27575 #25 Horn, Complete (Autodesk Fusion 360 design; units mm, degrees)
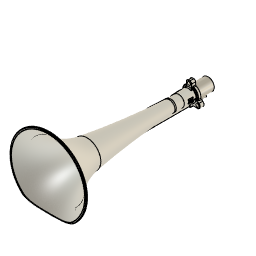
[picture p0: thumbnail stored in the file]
parameter "Bolt_Hole_Tolerance" = 1.5875 (= "( 1 / 16 ) * 1 in")
parameter "Dowel_Hole_Tolerance" = 0.0248 (= "( 1 / 1024 ) * 1 in")
canvas "Canvas1"
sketch "Main Profile" plane through (0, 0, 0) normal (1, 0, 0) x axis (0, 1, 0)
  line L1 (0, -22.225) -> (0, 22.225)
  line L2 (-53.975, 22.225) -> (0, 22.225)
  line L3 (-53.975, 44.45) -> (-53.975, 22.225)
  line L4 (-570.7062, 0) -> (0, 0)
  line L5 (-68.2625, 44.45) -> (-53.975, 44.45)
  line L6 (-53.975, -22.225) -> (0, -22.225)
  line L7 (-53.975, 22.225) -> (-53.975, -22.225)
  line L8 (-53.975, -38.1) -> (-53.975, -22.225)
  line L9 (-68.2625, -38.1) -> (-53.975, -38.1)
  line L10 (-68.2625, 44.45) -> (-68.2625, -38.1)
  line L11 (-138.2653, 17.1493) -> (0, 11.1125)
  line L12 (-63.5, 28.575) -> (-53.975, 28.575)
  line L13 (-63.5, 17.063) -> (-63.5, 28.575)
  line L14 (-138.1268, 20.3213) -> (-63.5, 17.063)
  line L15 (-570.7062, -136.525) -> (-570.7062, 136.525)
  line L16 (-68.2625, 17.2709) -> (-68.2625, 44.45)
  line L17 (9.1828, 34.925) -> (-68.2625, 34.925)
  line L18 (-34.1313, 22.225) -> (-34.1313, -22.225)
  line L19 (-431.6987, 0) -> (-431.6987, 46.0375)
  line L20 (-138.2653, -17.1493) -> (0, -11.1125)
  line L21 (-68.2625, -17.2709) -> (-68.2625, -38.1)
  line L22 (-68.2625, -17.2709) -> (-138.1268, -20.3213)
  line L23 (-532.6062, -136.525) -> (-570.7062, -136.525)
  line L24 (-532.6062, -123.825) -> (-532.6062, -136.525)
  line L25 (-570.7062, -123.825) -> (-532.6062, -123.825)
  line L26 (-570.7062, -136.525) -> (-570.7062, -123.825)
  line L27 (-565.9438, 136.525) -> (-570.7062, 136.525)
  line L28 (-565.9438, 129.9114) -> (-565.9438, 136.525)
  line L29 (-104.775, 20.1844) -> (-63.5, 22.225)
  line L30 (-324.4666, -34.925) -> (-68.2625, -34.925)
  arc A1 centre (-20.2125, 2721.0038) radius 2706.4304 clockwise from (-138.2653, 17.1493) to (-431.6987, 46.0375)
  arc A2 centre (-399.5974, 254.7204) radius 211.1375 clockwise from (-431.6987, 46.0375) to (-570.7062, 131.024)
  arc A3 centre (-20.2125, 2721.0038) radius 2703.2554 clockwise from (-138.1268, 20.3213) to (-431.216, 49.1756)
  arc A4 centre (-399.5974, 254.7204) radius 207.9625 clockwise from (-431.216, 49.1756) to (-570.7062, 136.525)
  arc A5 centre (-399.5974, -254.7204) radius 207.9625 clockwise from (-570.7062, -136.525) to (-431.216, -49.1756)
  arc A6 centre (-399.5974, -254.7204) radius 211.1375 clockwise from (-570.7062, -131.024) to (-431.6987, -46.0375)
  arc A7 centre (-20.2125, -2721.0038) radius 2703.2554 clockwise from (-431.216, -49.1756) to (-138.1268, -20.3213)
  arc A8 centre (-20.2125, -2721.0038) radius 2706.4304 clockwise from (-431.6987, -46.0375) to (-138.2653, -17.1493)
  arc A9 centre (-532.6062, -98.425) radius 38.1 clockwise from (-532.6062, -136.525) to (-570.7062, -98.425)
  arc A10 centre (-119.8256, 324.6126) radius 304.8 clockwise from (-104.775, 20.1844) to (-133.1208, 20.1027)
  point P4 (0, 0)
  point P1 (0, 0)
  point P7 (0, 0)
  point P13 (0, 11.1125)
  point P15 (-53.975, 28.575)
  point P21 (-570.7062, 0)
  point P8 (-570.7062, 0)
  point P22 (-68.2625, 17.2709)
  point P23 (-68.2625, 34.925)
  point P27 (-570.7062, 131.024)
  point P19 (-570.7062, 136.525)
  point P31 (-570.7062, 136.525)
  point P33 (-34.1313, -22.225)
  point P34 (-34.1313, 22.225)
  point P35 (-431.6987, 0)
  point P46 (0, -11.1125)
  point P14 (-138.2653, 17.1493)
  point P45 (-138.2653, -17.1493)
  point P18 (-138.1268, 20.3213)
  point P43 (-138.1268, -20.3213)
  point P25 (-431.6987, 46.0375)
  point P41 (-431.6987, -46.0375)
  point P40 (-570.7062, -131.024)
  point P29 (-431.216, 49.1756)
  point P38 (-431.216, -49.1756)
  point P37 (-570.7062, -136.525)
  point P47 (-68.2625, -17.2709)
  point P51 (-570.7062, -98.425)
  point P55 (-63.5, 22.225)
  point P57 (-68.2625, -34.925)
  point P59 (-133.1208, 20.1027)
  point P54 (-565.9438, 129.9114)
  point P58 (-324.4666, -34.925)
  point P2 (0, 22.225)
  point P5 (-53.975, 22.225)
  point P3 (0, -22.225)
  point P6 (-53.975, 44.45)
  point P9 (-68.2625, 44.45)
  point P16 (-63.5, 28.575)
  point P20 (-570.7062, -136.525)
  point P53 (-565.9438, 136.525)
  point P56 (-104.775, 20.1844)
  vertical L1
  coincident L1 P4
  coincident P1 P4
  midpoint P1 L1
  perpendicular L1 L2
  perpendicular L2 L3
  coincident P1 P7
  perpendicular L1 L4
  perpendicular L3 L5
  perpendicular L1 L6
  vertical L7
  perpendicular L6 L8
  perpendicular L8 L9
  vertical L10
  coincident L1 P13
  coincident L3 P15
  perpendicular L3 L12
  perpendicular L12 L13
  parallel L11 L14
  vertical L15
  midpoint L15 P21
  coincident P8 P21
  coincident L14 P22
  coincident L10 P22
  coincident L10 P23
  perpendicular L16 L17
  tangent L11 A1
  coincident L15 P27
  tangent A1 A2
  tangent L14 A3
  concentric A1 A3
  tangent A3 A4
  concentric A2 A4
  coincident P19 P31
  coincident L6 P33
  coincident L2 P34
  perpendicular L2 L18
  coincident L4 P35
  perpendicular L4 L19
  symmetric L4 P13 P46
  symmetric L4 P14 P45
  symmetric L4 P18 P43
  symmetric L4 P25 P41
  symmetric L4 A1 A8
  symmetric L4 P27 P40
  symmetric L4 A2 A6
  symmetric L4 P29 P38
  symmetric L4 A3 A7
  symmetric L4 P31 P37
  symmetric L4 A4 A5
  coincident L10 P47
  perpendicular L9 L21
  tangent A7 L22
  horizontal L23
  vertical L24
  horizontal L25
  vertical L26
  tangent L15 A9
  coincident L15 P51
  tangent L23 A9
  perpendicular L15 L27
  vertical L28
  coincident L13 P55
  coincident L10 P57
  horizontal L30
  coincident L14 P59
  tangent L29 A10
  tangent L14 A10
  coincident A4 P54
  coincident A7 P58
  dimension "d1" distance P2 P5 = 53.975 (= "2 1/8")
  dimension "d2" distance P2 P3 = 44.45 (= "1 3/4")
  dimension "d3" distance P6 L4 = 44.45 (= "1 3/4")
  dimension "d4" distance P6 P9 = 14.2875 (= "( 9 / 16 ) * 1 in")
  dimension "d5" distance L4 L9 = 38.1
  dimension "d6" distance P4 P13 = 11.1125 (= "( 7 / 16 ) * 1 in")
  dimension "d7" distance L11 L14 = 3.175 (= "( 1 / 8 ) * 1 in")
  dimension "d9" distance P15 P16 = 9.525 (= "( 3 / 8 ) * 1 in")
  dimension "d10" distance L4 L12 = 28.575
  dimension "d11" distance L4 L17 = 34.925 (= "1 3/8")
  dimension "d12" distance P19 P20 = 273.05 (= "10 3/4")
  dimension "d13" angle L4 L11 = 2.5
  dimension "d14" radius A1 = 2706.4304
  dimension "d15" radius A2 = 211.1375 (= "8 5/16")
  dimension "d17" distance L1 L18 = 34.1313 (= "1 11/32")
  dimension "d18" distance L15 L18 = 536.575 (= "21 1/8")
  dimension "d19" distance P25 P35 = 46.0375 (= "1 13/16")
  dimension "d23" distance L23 L25 = 12.7 (= "( 1 / 2 ) * 1 in")
  dimension "d24" radius A9 = 38.1 (= "1 1/2")
  dimension "d68" distance P19 P53 = 4.7625 (= "( 3 / 16 ) * 1 in")
  dimension "d114" distance P16 P55 = 6.35 (= "( 1 / 4 ) * 1 in")
  dimension "d115" distance L13 P56 = 41.275 (= "1 5/8")
  dimension "d117" distance L9 L30 = 3.175 (= "( 1 / 8 ) * 1 in")
  dimension "d153" radius A10 = 304.8
revolve "Revolve1" sketch "Main Profile" AlongAngle 360
extrude "Extrude1" cut sketch "Main Profile" profile of L15 A5 A6 L23 L24 L25 L26 A9 distance 139.7
sweep "Sweep5" sketch "Main Profile" TwistAngle 0 TaperAngle 0
sweep "Sweep6" TwistAngle 0 TaperAngle 0
mirror "Mirror3" mirrorStitchTolerance 0.1016
fillet "Fillet6" radius 101.6
fillet "Fillet8" radius 101.6
split "Split1"
remove_body "RemoveBody1"
delete_face "DeleteFace6"
delete_face "DeleteFace7"
mirror "Mirror4" mirrorStitchTolerance 0.1016
fillet "Fillet9" radius 1.5875 (= "( 1 / 16 ) * 1 in")
canvas "Canvas2"
sketch "Flange Profile" plane through (0, -53.975, 0) normal (0, 1, 0) x axis (-1, 0, 0)
  line L1 (0, 34.925) -> (0, 0)
  line L2 (0, 44.45) -> (0, 34.925)
  line L3 (3.175, 44.45) -> (-3.175, 44.45)
  line L4 (9.525, 31.1085) -> (9.525, 38.1)
  line L5 (-30.2459, -17.4625) -> (0, 0)
  line L6 (30.2459, -17.4625) -> (0, 0)
  line L7 (30.2459, -26.9875) -> (15.0812, -26.9875)
  line L8 (29.9633, -6.3008) -> (35.0084, -9.2136)
  line L9 (0, -31.75) -> (0, 0)
  line L10 (0, -38.1) -> (0, -31.75)
  line L11 (3.9688, -38.1) -> (-3.9688, -38.1)
  line L12 (15.0812, -26.9875) -> (3.9688, -38.1)
  line L13 (-15.0812, -26.9875) -> (-3.9688, -38.1)
  line L14 (-30.2459, -26.9875) -> (-15.0812, -26.9875)
  line L15 (-29.9633, -6.3008) -> (-35.0084, -9.2136)
  line L16 (-9.525, 31.1085) -> (-9.525, 38.1)
  line L17 (9.525, 20.0805) -> (9.525, 31.1085)
  line L18 (-9.525, 20.0805) -> (-9.525, 31.1085)
  line L19 (22.1527, -1.7913) -> (29.9633, -6.3008)
  line L20 (-22.1527, -1.7913) -> (-29.9633, -6.3008)
  circle C1 centre (0, 0) radius 22.225
  circle C2 centre (0, 34.925) radius 5.5563
  arc A1 centre (3.175, 38.1) radius 6.35 clockwise from (3.175, 44.45) to (9.525, 38.1)
  arc A2 centre (15.875, 31.1085) radius 6.35 clockwise from (12.9886, 25.4524) to (9.525, 31.1085)
  arc A3 centre (0, 0) radius 28.575 clockwise from (12.9886, 25.4524) to (28.3957, -3.196)
  circle C3 centre (-30.2459, -17.4625) radius 5.5563
  circle C4 centre (30.2459, -17.4625) radius 5.5563
  arc A4 centre (30.2459, -17.4625) radius 9.525 clockwise from (35.0084, -9.2136) to (30.2459, -26.9875)
  arc A5 centre (31.5508, -3.5512) radius 3.175 clockwise from (29.9633, -6.3008) to (28.3957, -3.196)
  circle C5 centre (0, -31.75) radius 3.9688
  arc A6 centre (-30.2459, -17.4625) radius 9.525 clockwise from (-30.2459, -26.9875) to (-35.0084, -9.2136)
  arc A7 centre (-31.5508, -3.5512) radius 3.175 clockwise from (-28.3957, -3.196) to (-29.9633, -6.3008)
  arc A8 centre (0, 0) radius 28.575 clockwise from (-28.3957, -3.196) to (-12.9886, 25.4524)
  arc A9 centre (-15.875, 31.1085) radius 6.35 clockwise from (-9.525, 31.1085) to (-12.9886, 25.4524)
  arc A10 centre (-3.175, 38.1) radius 6.35 clockwise from (-9.525, 38.1) to (-3.175, 44.45)
  circle C6 centre (0, 0) radius 28.575
  point P1 (0, 0)
  point P3 (0, 0)
  point P4 (0, 34.925)
  point P5 (0, 34.925)
  point P6 (0, 34.925)
  point P10 (0, 44.45)
  point P7 (0, 44.45)
  point P30 (0, 0)
  point P31 (0, -31.75)
  point P32 (0, -31.75)
  point P33 (0, -31.75)
  point P37 (0, -38.1)
  point P34 (0, -38.1)
  point P9 (3.175, 44.45)
  point P52 (-3.175, 44.45)
  point P11 (9.525, 38.1)
  point P50 (-9.525, 38.1)
  point P13 (9.525, 31.1085)
  point P49 (-9.525, 31.1085)
  point P14 (12.9886, 25.4524)
  point P47 (-12.9886, 25.4524)
  point P16 (28.3957, -3.196)
  point P45 (-28.3957, -3.196)
  point P24 (15.0812, -26.9875)
  point P39 (-15.0812, -26.9875)
  point P25 (30.2459, -26.9875)
  point P40 (-30.2459, -26.9875)
  point P26 (35.0084, -9.2136)
  point P42 (-35.0084, -9.2136)
  point P28 (29.9633, -6.3008)
  point P43 (-29.9633, -6.3008)
  point P36 (3.9688, -38.1)
  point P38 (-3.9688, -38.1)
  point P53 (9.525, 20.0805)
  point P54 (-9.525, 20.0805)
  point P55 (22.1527, -1.7913)
  point P56 (-22.1527, -1.7913)
  point P35 (-3.9688, -38.1)
  point P19 (0, 0)
  coincident P1 P3
  vertical L1
  coincident P4 P5
  coincident P5 P6
  parallel L1 L2
  horizontal L3
  coincident L3 P10
  midpoint L3 P10
  coincident P7 P10
  tangent L3 A1
  vertical L4
  tangent A1 L4
  tangent L4 A2
  tangent A2 A3
  concentric C1 A3
  horizontal L7
  tangent L7 A4
  concentric C4 A4
  tangent A4 L8
  tangent L8 A5
  tangent A3 A5
  coincident P1 P30
  vertical L9
  coincident P31 P32
  coincident P32 P33
  parallel L9 L10
  horizontal L11
  midpoint L11 P37
  coincident P34 P37
  symmetric L1 P9 P52
  symmetric L1 P11 P50
  symmetric L1 A1 A10
  symmetric L1 P13 P49
  symmetric L1 P14 P47
  symmetric L1 A2 A9
  symmetric L1 P16 P45
  symmetric L1 A3 A8
  symmetric L1 P24 P39
  symmetric L1 P25 P40
  symmetric L1 P26 P42
  symmetric L1 A4 A6
  symmetric L1 P28 P43
  symmetric L1 A5 A7
  symmetric L1 P36 P38
  coincident C1 P53
  tangent A2 L17
  tangent A9 L18
  coincident C1 P54
  coincident C1 P55
  tangent A5 L19
  coincident C1 P56
  tangent A7 L20
  dimension "d95" distance P3 P4 = 34.925 (= "1 3/8")
  dimension "d96" diameter C2 = 11.1125 (= "( 3 / 8 ) * 1 in + Bolt_Hole_Tolerance")
  dimension "d97" radius A1 = 6.35 (= "( 1 / 4 ) * 1 in")
  dimension "d98" distance P1 L3 = 44.45 (= "1 3/4")
  dimension "d99" distance P5 L4 = 9.525 (= "( 3 / 8 ) * 1 in")
  dimension "d100" radius A2 = 6.35 (= "( 1 / 4 ) * 1 in")
  dimension "d101" radius A3 = 28.575 (= "1 1/8")
  dimension "d104" radius A4 = 9.525 (= "( 3 / 8 ) * 1 in")
  dimension "d105" angle L7 L8 = 30
  dimension "d106" radius A5 = 3.175 (= "( 1 / 8 ) * 1 in")
  dimension "d107" distance P30 P31 = 31.75 (= "1 1/4")
  dimension "d108" diameter C5 = 7.9375 (= "( 5 / 16 ) * 1 in")
  dimension "d109" distance P35 P36 = 7.9375 (= "( 5 / 16 ) * 1 in")
  dimension "d110" angle L7 L12 = 135
  dimension "d111" distance P19 L11 = 38.1 (= "1 1/2")
  dimension "d103" C-Pattern1-Angle = 360
extrude "Extrude2" add sketch "Flange Profile" profile of C1 C2 L3 A1 L4 C3 C4 L7 A4 L8 C5 L11 L12 L13 L14 A6 L15 L16 A10 L17 L18 L19 L20 against normal blind 14.2875 (magnitude of "( -9 / 16 ) * 1 in")
delete_face "DeleteFace8"
extrude "Extrude3" add sketch "Main Profile" profile of A7 L21 L22 L30 distance 6.35 (= "( 1 / 4 ) * 1 in")
delete_face "DeleteFace9"
fillet "Fillet10" radius 304.8
fillet "Fillet11" radius 3.175 (= "( 1 / 8 ) * 1 in")
fillet "Fillet12" radius 1.5875 (= "( 1 / 16 ) * 1 in")
fillet "Fillet13" radius 3.175 (= "( 1 / 8 ) * 1 in")
fillet "Fillet14" radius 1.5875 (= "( 1 / 16 ) * 1 in")
fillet "Fillet15" radius 0.7937 (= "( 1 / 32 ) * 1 in")
extrude "Extrude4" cut sketch "Flange Profile" profile of C2 C3 C4 against normal blind 14.3002
extrude "Extrude5" cut sketch "Flange Profile" profile of C5 against normal blind 9.525 (magnitude of "( -3 / 8 ) * 1 in")
sketch "Main Profile" plane through (0, -63.5, 0) normal (0, 1, 0) x axis (-1, 0, 0)
  circle C1 centre (0, -31.75) radius 3.9687
  circle C2 centre (0, -31.75) radius 3.175
  concentric C1 C2
  dimension "d137" diameter C2 = 6.35 (= "( 1 / 4 ) * 1 in")
extrude "Extrude1" new body sketch "Main Profile" along normal blind 53.975 (= "2 1/8") bodies "27284 Orifice Pin #2"
offset_faces "OffsetFaces1"
work_plane "WorkPlane1" RotateAngle -180
sketch "Orifice & Number Profile" plane through (0, -43.2509, -35.7188) normal (0, 0, -1) x axis (1, 0, 0)
  line L1 (3.9688, -33.7259) -> (-3.9687, -33.7259)
  line L2 (3.9688, 20.2491) -> (-3.9687, 20.2491)
  line L3 (0, 20.2491) -> (0, -33.7259)
  line L4 (-22.225, -43.2509) -> (22.225, -43.2509)
  line L5 (1.5875, -9.1196) -> (1.5875, -33.7259)
  line L6 (0, -9.1196) -> (1.5875, -9.1196)
  circle C1 centre (0, -9.1196) radius 1.5875
  point P6 (0, -33.7259)
  point P7 (0, 20.2491)
  point P8 (0, -9.1196)
  point P11 (1.5875, -33.7259)
  point P13 (0, -9.1196)
  point P12 (1.5875, -9.1196)
  midpoint L1 P6
  midpoint L2 P7
  coincident L3 P8
  coincident L1 P11
  perpendicular L1 L5
  coincident L3 P13
  perpendicular L3 L6
  coincident P8 P13
  dimension "d143" diameter C1 = 3.175 (= "( 1 / 8 ) * 1 in")
  dimension "d144" distance P8 L4 = 34.1313
  dimension "d145" distance P12 P13 = 1.5875 (= "( 1 / 16 ) * 1 in")
  dimension "d146" Text1-Height = 3.175 (= "( 1 / 8 ) * 1 in")
emboss "Emboss1" sketch "Orifice & Number Profile" Depth -0.1984 (= "( -1 / 128 ) * 1 in") Horizontal Distance 0 Vertical Distance 0 Rotation Angle 0
extrude "Extrude2" cut sketch "Orifice & Number Profile" profile of C1 against normal blind 3.175 (magnitude of "( -1 / 8 ) * 1 in")
sketch "Branding Profile 1" plane through (0, 0, 0) normal (0, 0, 1) x axis (1, 0, 0)
  line L1 (49.1756, -431.216) -> (-49.1756, -431.216)
  curve K1 (-4.4177, -138.1268) -> (-4.5392, -298.3662)
  curve K2 (-4.5392, -298.3662) -> (-4.4127, -306.9422)
  curve K3 (-4.4127, -306.9422) -> (-1.6572, -346.2553)
  curve K4 (-1.6572, -346.2553) -> (1.6572, -346.2553)
  curve K5 (1.6572, -346.2553) -> (4.4127, -306.9422)
  curve K6 (4.4127, -306.9422) -> (4.5392, -298.3662)
  curve K7 (4.5392, -298.3662) -> (4.4177, -138.1268)
  line L2 (20.3213, -138.1268) -> (-20.3213, -138.1268)
  line L3 (-4.4142, -133.1208) -> (-4.4177, -138.1268)
  line L4 (20.3213, -138.1268) -> (-20.3213, -138.1268)
  line L5 (4.4177, -138.1268) -> (4.4142, -133.1208)
  line L6 (20.1027, -133.1208) -> (-20.1027, -133.1208)
  curve K8 (-4.4156, -104.775) -> (-4.4142, -133.1208)
  line L7 (20.1027, -133.1208) -> (-20.1027, -133.1208)
  curve K9 (4.4142, -133.1208) -> (4.4156, -104.775)
  line L8 (20.1844, -104.775) -> (-20.1844, -104.775)
  line L9 (-10.3604, -71.2807) -> (10.3604, -71.2807)
  curve K10 (-10.3604, -71.2807) -> (-10.3702, -65.0091)
  line L10 (-22.1504, -65.0091) -> (-10.3702, -65.0091)
  curve K11 (-22.1357, -65.0091) -> (-21.8309, -71.2807)
  line L11 (-21.8309, -71.2807) -> (-4.4402, -71.2807)
  curve K12 (-4.4402, -71.2807) -> (-4.4156, -104.775)
  line L12 (20.1844, -104.775) -> (-20.1844, -104.775)
  curve K13 (4.4156, -104.775) -> (4.4402, -71.2807)
  line L13 (4.4402, -71.2807) -> (21.8309, -71.2807)
  curve K14 (21.8309, -71.2807) -> (22.1357, -65.0091)
  line L14 (10.3702, -65.0091) -> (22.1504, -65.0091)
  curve K15 (10.3702, -65.0091) -> (10.3604, -71.2807)
  line L15 (-20.1844, -104.775) -> (-21.8309, -71.2807)
  line L16 (-21.7878, -76.2) -> (-20.0037, -76.1192)
  line L17 (-20.0636, -114.261) -> (-21.7878, -76.2)
  line L18 (-18.2795, -114.1801) -> (-20.0636, -114.261)
  line L19 (-20.0037, -76.1192) -> (-18.2795, -114.1801)
  line L20 (-24.6635, -68.2625) -> (-34.6116, -68.2625)
  line L21 (-20.0959, -126.961) -> (-18.3123, -127.0528)
  line L22 (-23.5228, -193.5478) -> (-20.0959, -126.961)
  line L23 (-21.7392, -193.6396) -> (-23.5228, -193.5478)
  line L24 (-18.3123, -127.0528) -> (-21.7392, -193.6396)
  line L25 (0, 15.24) -> (0, 0)
  line L26 (20.1844, -104.775) -> (21.8309, -71.2807)
  line L27 (20.004, -76.1123) -> (21.7878, -76.2)
  line L28 (19.3804, -88.797) -> (20.004, -76.1123)
  line L29 (21.1642, -88.8847) -> (19.3804, -88.797)
  line L30 (21.7878, -76.2) -> (21.1642, -88.8847)
  line L31 (34.6116, -68.2625) -> (24.6635, -68.2625)
  arc A1 centre (-326.4604, -119.8309) radius 306.6458 clockwise from (-20.1844, -104.775) to (-20.1027, -133.1208)
  arc A2 centre (-8953.3117, 254.4038) radius 8941.6105 clockwise from (-20.1027, -133.1208) to (-20.3213, -138.1268)
  arc A3 centre (-2734.9134, -18.8431) radius 2717.2117 clockwise from (-20.3213, -138.1268) to (-49.1756, -431.216)
  arc A4 centre (326.4604, -119.8309) radius 306.6458 clockwise from (20.1027, -133.1208) to (20.1844, -104.775)
  arc A5 centre (2734.9134, -18.8431) radius 2717.2117 clockwise from (49.1756, -431.216) to (20.3213, -138.1268)
  arc A6 centre (8953.3117, 254.4038) radius 8941.6105 clockwise from (20.3213, -138.1268) to (20.1027, -133.1208)
  point P34 (-21.8309, -71.2807)
  point P46 (-21.8309, -71.2807)
  point P28 (-20.1844, -104.775)
  point P47 (-20.1844, -104.775)
  point P20 (-20.1027, -133.1208)
  point P48 (-20.1027, -133.1208)
  point P12 (-20.3213, -138.1268)
  point P50 (-20.3213, -138.1268)
  point P2 (-49.1756, -431.216)
  point P53 (-49.1756, -431.216)
  point P52 (-20.3213, -138.1268)
  point P59 (-21.5895, -76.191)
  point P60 (-19.8653, -114.252)
  point P67 (-23.3246, -193.558)
  point P68 (-19.8977, -126.9712)
  point P1 (0, 0)
  point P69 (0, 0)
  point P71 (21.8309, -71.2807)
  point P72 (20.1844, -104.775)
  point P74 (20.1027, -133.1208)
  point P79 (20.3213, -138.1268)
  point P77 (20.3213, -138.1268)
  point P76 (49.1756, -431.216)
  point P84 (21.5896, -76.1903)
  point P85 (20.966, -88.8749)
  point P57 (-20.0636, -114.261)
  point P56 (-21.7878, -76.2)
  point P64 (-20.0959, -126.961)
  point P65 (-23.5228, -193.5478)
  point P66 (-21.7392, -193.6396)
  point P80 (21.7878, -76.2)
  point P83 (21.1642, -88.8847)
  coincident P34 P46
  coincident P28 P47
  tangent L15 A1
  coincident P20 P48
  coincident P12 P50
  tangent A1 A2
  coincident P2 P53
  coincident P12 P52
  tangent A2 A3
  perpendicular L17 L18
  perpendicular L16 L17
  perpendicular L16 L19
  coincident L16 P59
  coincident L15 P59
  coincident A1 P60
  coincident L18 P60
  perpendicular L21 L22
  perpendicular L22 L23
  perpendicular L23 L24
  coincident A3 P67
  coincident L23 P67
  coincident A1 P68
  coincident L21 P68
  coincident P1 P69
  vertical L25
  symmetric P46 L25 P71
  symmetric P47 L25 P72
  symmetric P48 L25 P74
  symmetric A1 L25 A4
  symmetric P50 L25 P79
  symmetric A2 L25 A6
  symmetric P52 L25 P77
  symmetric P53 L25 P76
  symmetric A3 L25 A5
  perpendicular L26 L27
  perpendicular L27 L28
  perpendicular L26 L29
  perpendicular L29 L30
  coincident L27 P84
  coincident L26 P84
  coincident L29 P85
  coincident L26 P85
  dimension "d154" distance P57 P60 = 0.1984 (= "( 1 / 128 ) * 1 in")
  dimension "d155" distance P56 P59 = 0.1984 (= "d154")
  dimension "d156" distance P56 L20 = 7.9375 (= "( 5 / 16 ) * 1 in")
  dimension "d157" distance L19 P59 = 1.5875 (= "( 1 / 16 ) * 1 in")
  dimension "d158" distance P56 P57 = 38.1 (= "1 1/2")
  dimension "d159" distance P64 P68 = 0.1984 (= "d160")
  dimension "d160" distance P65 P67 = 0.1984 (= "( 1 / 128 ) * 1 in")
  dimension "d161" distance P66 P67 = 1.5875 (= "( 1 / 16 ) * 1 in")
  dimension "d162" distance P57 P64 = 12.7 (= "( 1 / 2 ) * 1 in")
  dimension "d163" distance P64 P65 = 66.675 (= "2 5/8")
  dimension "d164" distance L30 P84 = 0.1984 (= "( 1 / 128 ) * 1 in")
  dimension "d165" distance L26 L28 = 1.5875 (= "( 1 / 16 ) * 1 in")
  dimension "d166" distance P80 L31 = 7.9375 (= "( 5 / 16 ) * 1 in")
  dimension "d167" distance P80 P83 = 12.7 (= "( 1 / 2 ) * 1 in")
extrude "Extrude6" add sketch "Branding Profile 1" profile of L2 L4 L6 L7 L8 L12 L15 A1 A2 A3 L16 L17 L18 L19 L21 L22 L23 L24 distance 19.05 (= "( 3 / 4 ) * 1 in")
delete_face "DeleteFace10"
extrude "Extrude7" add sketch "Branding Profile 1" profile of L26 L27 L28 L29 L30 distance 9.525 (= "( 3 / 8 ) * 1 in")
fillet "Fillet16" radius 6.35 (= "( 1 / 4 ) * 1 in")
fillet "Fillet17" radius 3.175 (= "( 1 / 8 ) * 1 in")
fillet "Fillet18" radius 0.7937 (= "( 1 / 32 ) * 1 in")
sketch "Branding Profile 2" plane through (-25.188, -1.1411, 0) normal (-0.999, -0.0453, 0) x axis (0.0453, -0.999, 0)
  curve K1 (75.1359, -8.7898) -> (75.9363, -9.525)
  line L1 (104.0174, -9.525) -> (75.9363, -9.525)
  line L2 (112.415, -9.525) -> (104.0174, -9.525)
  curve K2 (112.415, -9.525) -> (113.2359, -8.7717)
  line L3 (113.2359, 8.7717) -> (113.2359, -8.7717)
  curve K3 (113.2359, 8.7717) -> (112.415, 9.525)
  line L4 (104.0174, 9.525) -> (112.415, 9.525)
  line L5 (75.9363, 9.525) -> (104.0174, 9.525)
  curve K4 (75.9363, 9.525) -> (75.1359, 8.7898)
  line L6 (75.1359, -8.7898) -> (75.1359, 8.7898)
  line L7 (93.251, 3.8359) -> (93.3442, 3.2617)
  line L8 (93.3764, -4.2813) -> (93.3764, -2.0198)
  line L9 (100.3887, -6.011) -> (97.0133, -5.5871)
  line L10 (94.139, 5.2738) -> (91.0873, 5.2738)
  line L11 (94.8829, -5.0326) -> (94.8829, -1.5281)
  line L12 (94.5336, 3.3576) -> (94.5336, 4.8791)
  line L13 (105.4604, -6.6138) -> (105.4604, 6.9982)
  line L14 (103.2461, -6.7165) -> (102.4928, -6.4572)
  line L15 (108.3757, -0.592) -> (108.3757, 0.1613)
  line L16 (109.6737, -8.4438) -> (109.6737, -7.6149)
  line L17 (103.7454, 6.3232) -> (103.7454, -6.3604)
  line L18 (107.4715, -0.9686) -> (107.999, -0.9686)
  line L19 (107.0949, -5.948) -> (107.0949, -1.3453)
  line L20 (109.5803, 7.8519) -> (109.5803, 8.6696)
  line L21 (107.0949, 0.9145) -> (107.0949, 6.3029)
  line L22 (102.4928, 6.42) -> (103.2461, 6.6793)
  line L23 (92.3058, 4.1584) -> (92.8719, 4.1584)
  line L24 (107.0949, 0.9145) -> (107.0949, -1.3453)
  line L25 (107.999, 0.5379) -> (107.4715, 0.5379)
  line L26 (100.8123, -4.8781) -> (100.8123, -5.6373)
  line L27 (102.2388, -6.1011) -> (102.2388, 6.0639)
  line L28 (97.8604, -3.8429) -> (97.8604, 5.1103)
  line L29 (98.1902, -4.2166) -> (100.4826, -4.5044)
  line L30 (94.5928, -0.6393) -> (92.0053, 2.9021)
  line L31 (97.4838, 5.487) -> (96.7305, 5.487)
  line L32 (96.3539, -4.8397) -> (96.3539, 5.1103)
  line L33 (92.9923, -4.6653) -> (92.0272, -4.6653)
  line L34 (91.2758, -5.4092) -> (94.5063, -5.4092)
  line L35 (87.1003, 4.6563) -> (88.4353, 4.3319)
  line L36 (88.6887, 5.7567) -> (85.3656, 6.5641)
  line L37 (89.1011, 4.8553) -> (89.1011, 5.2322)
  line L38 (91.9218, 3.5592) -> (91.9218, 3.7743)
  line L39 (105.8994, -7.2984) -> (109.1399, -8.7861)
  line L40 (86.2306, 1.0264) -> (86.2306, 3.9726)
  line L41 (90.6166, 2.3877) -> (90.6166, 4.8031)
  line L42 (91.9218, 3.158) -> (91.9218, 3.5592)
  line L43 (107.325, 6.6498) -> (109.3502, 7.5049)
  line L44 (80.4244, 8.1969) -> (79.8041, 8.6312)
  line L45 (87.0587, 0.5429) -> (86.7141, 0.5429)
  line L46 (89.3306, -5.0959) -> (89.3306, -5.528)
  line L47 (88.9498, -6.0315) -> (85.5568, -6.9922)
  line L48 (87.5422, -0.4801) -> (87.5422, 0.0594)
  line L49 (86.7141, -0.9636) -> (87.0587, -0.9636)
  line L50 (91.6431, -4.2813) -> (91.6431, -2.0448)
  line L51 (90.8992, -2.0448) -> (90.8992, -5.0326)
  line L52 (86.2306, 1.0264) -> (86.2306, -1.4472)
  line L53 (83.3482, -6.7697) -> (83.3482, -7.1367)
  line L54 (84.7241, -6.3626) -> (84.7241, 6.0597)
  line L55 (109.0571, 9.0165) -> (105.9207, 7.6922)
  line L56 (87.0677, -5.0926) -> (88.7109, -4.6273)
  line L57 (109.4542, -7.2726) -> (107.3144, -6.2903)
  line L58 (91.2665, -1.6682) -> (91.2758, -1.6682)
  line L59 (81.392, -6.7702) -> (82.4605, -6.2258)
  line L60 (86.2306, -4.4596) -> (86.2306, -1.4472)
  line L61 (80.6263, -6.301) -> (80.6263, 7.809)
  line L62 (82.9551, -7.7782) -> (80.241, -9.1611)
  line L63 (93.0863, -1.131) -> (90.6984, 2.1371)
  line L64 (78.9918, -8.3956) -> (78.9918, 8.2084)
  arc A1 centre (92.9923, -4.2813) radius 0.3841 clockwise from (93.3764, -4.2813) to (92.9923, -4.6653)
  arc A2 centre (94.5063, -5.0326) radius 0.3766 clockwise from (94.8829, -5.0326) to (94.5063, -5.4092)
  arc A3 centre (93.9351, 3.3576) radius 0.5986 clockwise from (94.5336, 3.3576) to (93.3442, 3.2617)
  arc A4 centre (91.0414, 2.3877) radius 0.4248 clockwise from (90.6984, 2.1371) to (90.6166, 2.3877)
  arc A5 centre (109.2036, 7.8519) radius 0.3766 clockwise from (109.5803, 7.8519) to (109.3502, 7.5049)
  arc A6 centre (100.4357, -5.6373) radius 0.3766 clockwise from (100.8123, -5.6373) to (100.3887, -6.011)
  arc A7 centre (109.2971, -7.6149) radius 0.3766 clockwise from (109.4542, -7.2726) to (109.6737, -7.6149)
  arc A8 centre (102.6155, 6.0639) radius 0.3766 clockwise from (102.2388, 6.0639) to (102.4928, 6.42)
  arc A9 centre (109.2036, 8.6696) radius 0.3766 clockwise from (109.0571, 9.0165) to (109.5803, 8.6696)
  arc A10 centre (107.4715, -5.948) radius 0.3766 clockwise from (107.3144, -6.2903) to (107.0949, -5.948)
  arc A11 centre (109.2971, -8.4438) radius 0.3766 clockwise from (109.6737, -8.4438) to (109.1399, -8.7861)
  arc A12 centre (107.4715, 0.9145) radius 0.3766 clockwise from (107.4715, 0.5379) to (107.0949, 0.9145)
  arc A13 centre (107.4715, -1.3453) radius 0.3766 clockwise from (107.0949, -1.3453) to (107.4715, -0.9686)
  arc A14 centre (102.6155, -6.1011) radius 0.3766 clockwise from (102.4928, -6.4572) to (102.2388, -6.1011)
  arc A15 centre (100.4357, -4.8781) radius 0.3766 clockwise from (100.4826, -4.5044) to (100.8123, -4.8781)
  arc A16 centre (106.2137, 6.9982) radius 0.7533 clockwise from (105.4604, 6.9982) to (105.9207, 7.6922)
  arc A17 centre (103.3687, 6.3232) radius 0.3766 clockwise from (103.2461, 6.6793) to (103.7454, 6.3232)
  arc A18 centre (94.139, 4.8791) radius 0.3947 clockwise from (94.139, 5.2738) to (94.5336, 4.8791)
  arc A19 centre (92.8719, 3.7743) radius 0.3841 clockwise from (92.8719, 4.1584) to (93.251, 3.8359)
  arc A20 centre (103.3687, -6.3604) radius 0.3766 clockwise from (103.7454, -6.3604) to (103.2461, -6.7165)
  arc A21 centre (106.2137, -6.6138) radius 0.7533 clockwise from (105.8994, -7.2984) to (105.4604, -6.6138)
  arc A22 centre (97.4838, 5.1103) radius 0.3766 clockwise from (97.4838, 5.487) to (97.8604, 5.1103)
  arc A23 centre (97.1072, -4.8397) radius 0.7533 clockwise from (97.0133, -5.5871) to (96.3539, -4.8397)
  arc A24 centre (107.4715, 6.3029) radius 0.3766 clockwise from (107.0949, 6.3029) to (107.325, 6.6498)
  arc A25 centre (98.2371, -3.8429) radius 0.3766 clockwise from (98.1902, -4.2166) to (97.8604, -3.8429)
  arc A26 centre (96.7305, 5.1103) radius 0.3766 clockwise from (96.3539, 5.1103) to (96.7305, 5.487)
  arc A27 centre (91.8698, -2.0198) radius 1.5065 clockwise from (93.0863, -1.131) to (93.3764, -2.0198)
  arc A28 centre (93.3764, -1.5281) radius 1.5065 clockwise from (94.5928, -0.6393) to (94.8829, -1.5281)
  arc A29 centre (92.3556, 3.158) radius 0.4338 clockwise from (92.0053, 2.9021) to (91.9218, 3.158)
  arc A30 centre (86.9342, 3.9726) radius 0.7035 clockwise from (86.2306, 3.9726) to (87.1003, 4.6563)
  arc A31 centre (88.5625, 4.8553) radius 0.5386 clockwise from (89.1011, 4.8553) to (88.4353, 4.3319)
  arc A32 centre (88.5613, 5.2322) radius 0.5398 clockwise from (88.6887, 5.7567) to (89.1011, 5.2322)
  arc A33 centre (92.3058, 3.7743) radius 0.3841 clockwise from (91.9218, 3.7743) to (92.3058, 4.1584)
  arc A34 centre (82.6283, -7.1367) radius 0.7199 clockwise from (83.3482, -7.1367) to (82.9551, -7.7782)
  arc A35 centre (80.1528, 7.809) radius 0.4736 clockwise from (80.4244, 8.1969) to (80.6263, 7.809)
  arc A36 centre (79.508, 8.2084) radius 0.5162 clockwise from (78.9918, 8.2084) to (79.8041, 8.6312)
  arc A37 centre (86.7141, -1.4472) radius 0.4835 clockwise from (86.2306, -1.4472) to (86.7141, -0.9636)
  arc A38 centre (85.2431, 6.0597) radius 0.519 clockwise from (84.7241, 6.0597) to (85.3656, 6.5641)
  arc A39 centre (91.0873, 4.8031) radius 0.4706 clockwise from (90.6166, 4.8031) to (91.0873, 5.2738)
  arc A40 centre (82.7377, -6.7697) radius 0.6105 clockwise from (82.4605, -6.2258) to (83.3482, -6.7697)
  arc A41 centre (92.0272, -4.2813) radius 0.3841 clockwise from (92.0272, -4.6653) to (91.6431, -4.2813)
  arc A42 centre (91.2758, -2.0448) radius 0.3766 clockwise from (90.8992, -2.0448) to (91.2758, -1.6682)
  arc A43 centre (87.0587, 0.0594) radius 0.4835 clockwise from (87.0587, 0.5429) to (87.5422, 0.0594)
  arc A44 centre (91.2665, -2.0448) radius 0.3766 clockwise from (91.2665, -1.6682) to (91.6431, -2.0448)
  arc A45 centre (87.0587, -0.4801) radius 0.4835 clockwise from (87.5422, -0.4801) to (87.0587, -0.9636)
  arc A46 centre (81.1529, -6.301) radius 0.5266 clockwise from (81.392, -6.7702) to (80.6263, -6.301)
  arc A47 centre (79.851, -8.3956) radius 0.8592 clockwise from (80.241, -9.1611) to (78.9918, -8.3956)
  arc A48 centre (85.3785, -6.3626) radius 0.6544 clockwise from (85.5568, -6.9922) to (84.7241, -6.3626)
  arc A49 centre (88.8072, -5.528) radius 0.5233 clockwise from (89.3306, -5.528) to (88.9498, -6.0315)
  arc A50 centre (86.7141, 1.0264) radius 0.4835 clockwise from (86.7141, 0.5429) to (86.2306, 1.0264)
  arc A51 centre (88.8436, -5.0959) radius 0.487 clockwise from (88.7109, -4.6273) to (89.3306, -5.0959)
  arc A52 centre (86.8885, -4.4596) radius 0.6578 clockwise from (87.0677, -5.0926) to (86.2306, -4.4596)
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  point P58 (80.6263, -6.301)
  point P175 (80.6263, -6.301)
  point P136 (97.8604, -3.8429)
  point P137 (97.8604, -3.8429)
  point P88 (108.3757, -0.2154)
  point P31 (105.4604, -6.6138)
  point P142 (105.4604, -6.6138)
  tangent A36 L64
  tangent A36 L44
  tangent A35 L44
  tangent A35 L61
  vertical L61
  tangent A47 L64
  tangent A47 L62
  tangent A34 L62
  vertical L53
  tangent A34 L53
  tangent A40 L53
  tangent A40 L59
  parallel L59 L62
  tangent A46 L59
  coincident P58 P175
  tangent A46 L61
  vertical L54
  tangent A38 L54
  tangent L36 A38
  tangent L36 A32
  tangent L37 A32
  vertical L37
  tangent L37 A31
  tangent L35 A31
  parallel L35 L36
  tangent L35 A30
  vertical L40
  tangent A30 L40
  tangent L40 A50
  tangent L45 A50
  horizontal L45
  tangent L45 A43
  tangent A43 L48
  vertical L48
  tangent L48 A45
  horizontal L49
  tangent A45 L49
  tangent A37 L49
  vertical L60
  tangent A37 L60
  vertical L52
  tangent A48 L54
  tangent L47 A48
  tangent L47 A49
  vertical L46
  tangent L46 A49
  tangent L46 A51
  tangent L56 A51
  tangent L56 A52
  tangent A52 L60
  parallel L47 L56
  horizontal L10
  tangent L10 A18
  vertical L12
  tangent L12 A18
  tangent A3 L12
  tangent L7 A3
  tangent L7 A19
  tangent L23 A19
  horizontal L23
  tangent L23 A33
  vertical L38
  tangent L38 A33
  tangent L10 A39
  vertical L41
  tangent L41 A39
  tangent A4 L41
  tangent A4 L63
  parallel L38 L42
  tangent A29 L42
  tangent L30 A29
  parallel L30 L63
  tangent L30 A28
  vertical L11
  tangent L11 A28
  tangent A27 L63
  tangent L8 A27
  vertical L8
  tangent L11 A2
  horizontal L34
  tangent A2 L34
  vertical L51
  tangent A42 L51
  horizontal L58
  tangent A42 L58
  tangent A44 L58
  vertical L50
  tangent A44 L50
  tangent A41 L50
  tangent L8 A1
  tangent L33 A41
  tangent A1 L33
  vertical L32
  tangent L32 A26
  horizontal L31
  tangent L31 A26
  tangent A22 L31
  vertical L28
  tangent L28 A22
  tangent L32 A23
  tangent L9 A23
  tangent L9 A6
  vertical L26
  tangent A6 L26
  tangent A15 L26
  tangent A15 L29
  parallel L9 L29
  tangent L29 A25
  coincident P136 P137
  tangent L28 A25
  vertical L27
  tangent A14 L27
  tangent L14 A14
  tangent L14 A20
  vertical L17
  tangent L17 A20
  tangent L17 A17
  tangent L22 A17
  tangent A8 L22
  tangent A8 L27
  tangent L13 A16
  tangent A16 L55
  tangent A9 L55
  tangent A9 L20
  vertical L20
  tangent A5 L20
  tangent A5 L43
  parallel L43 L55
  tangent A24 L43
  vertical L21
  tangent L21 A24
  tangent A12 L21
  horizontal L25
  tangent A12 L25
  vertical L15
  horizontal L18
  tangent L18 A13
  vertical L19
  tangent L19 A13
  vertical L24
  midpoint P88 L15
  tangent A10 L19
  tangent A10 L57
  tangent A7 L57
  vertical L16
  tangent A7 L16
  tangent L16 A11
  tangent A11 L39
  parallel L39 L57
  tangent A21 L39
  coincident P31 P142
  tangent L13 A21
  dimension "d357" angle L44 L64 = 55
  dimension "d359" angle L62 L64 = 63
  dimension "d367" angle L7 L12 = 9.219
  dimension "d371" radius A4 = 0.4248
  dimension "d384" distance L10 L23 = 1.1154
  dimension "d395" angle L14 L27 = 109
  dimension "d400" angle L22 L27 = 109
  dimension "d339" angle L16 L57 = 114.659
extrude "Extrude8" add sketch "Branding Profile 2" along normal blind 0.3969 (= "( 1 / 64 ) * 1 in") taper -30
sketch "Branding Profile 3" plane through (-13.526, 0.6961, 0) normal (-0.9987, 0.0514, 0) x axis (-0.0514, -0.9987, 0)
  curve K1 (193.7146, -9.525) -> (194.501, -8.8072)
  line L1 (194.501, 8.8072) -> (194.501, -8.8072)
  curve K2 (194.501, 8.8072) -> (193.7146, 9.525)
  line L2 (138.7708, 9.525) -> (193.7146, 9.525)
  line L3 (133.7572, 9.525) -> (138.7708, 9.525)
  line L4 (128.6467, 9.525) -> (133.7572, 9.525)
  curve K3 (128.6467, 9.525) -> (127.826, 8.7723)
  line L5 (127.826, -8.7723) -> (127.826, 8.7723)
  curve K4 (127.826, -8.7723) -> (128.6467, -9.525)
  line L6 (133.7572, -9.525) -> (128.6467, -9.525)
  line L7 (138.7708, -9.525) -> (133.7572, -9.525)
  line L8 (193.7146, -9.525) -> (138.7708, -9.525)
  line L9 (127.826, 0) -> (194.501, 0)
  line L10 (194.501, -3.175) -> (127.826, -3.175)
  line L11 (161.1635, -4.7625) -> (129.0694, -4.7625)
  line L12 (161.1635, -5.9531) -> (161.1635, -4.7625)
  line L13 (129.0694, -5.9531) -> (161.1635, -5.9531)
  line L14 (129.0694, -4.7625) -> (129.0694, -5.9531)
  line L15 (161.1635, 0) -> (161.1635, -4.7625)
  line L16 (129.0694, 0) -> (129.0694, -4.7625)
  point P14 (194.501, 0)
  point P15 (127.826, 0)
  point P16 (127.826, -3.175)
  point P17 (194.501, -3.175)
  point P22 (161.1635, 0)
  point P23 (129.0694, 0)
  point P18 (129.0694, -4.7625)
  point P21 (129.0694, -5.9531)
  midpoint L1 P14
  midpoint L5 P15
  coincident L5 P16
  coincident L1 P17
  perpendicular L1 L10
  horizontal L11
  vertical L12
  horizontal L13
  vertical L14
  midpoint L9 P22
  perpendicular L9 L15
  coincident L9 P23
  perpendicular L9 L16
  dimension "d188" distance L9 L10 = 3.175 (= "( 1 / 8 ) * 1 in")
  dimension "d190" distance L10 L11 = 1.5875 (= "( 1 / 16 ) * 1 in")
  dimension "d191" distance P18 P21 = 1.1906 (= "( 3 / 64 ) * 1 in")
  dimension "d189" Text1-Height = 9.525 (= "( 3 / 8 ) * 1 in")
extrude "Extrude9" add sketch "Branding Profile 3" profile of L11 L12 L13 L14 along normal blind 0.3969 (= "( 1 / 64 ) * 1 in") taper -25
sketch "Branding Profile 4" plane through (25.4721, -1.2522, 0) normal (0.9988, -0.0491, 0) x axis (0.0491, 0.9988, 0)
  curve K1 (-75.5941, -4.7625) -> (-75.0383, -4.2995)
  line L1 (-75.0383, 4.2995) -> (-75.0383, -4.2995)
  curve K2 (-75.0383, 4.2995) -> (-75.5941, 4.7625)
  line L2 (-87.1742, 4.7625) -> (-75.5941, 4.7625)
  curve K3 (-87.1742, 4.7625) -> (-87.7383, 4.2931)
  line L3 (-87.7383, -4.2931) -> (-87.7383, 4.2931)
  curve K4 (-87.7383, -4.2931) -> (-87.1742, -4.7625)
  line L4 (-75.5941, -4.7625) -> (-87.1742, -4.7625)
  line L5 (-75.0383, 0) -> (-87.7383, 0)
  line L6 (-87.7383, -3.175) -> (-75.0383, -3.175)
  point P10 (-87.7383, 0)
  point P11 (-75.0383, 0)
  point P12 (-75.0383, -3.175)
  point P13 (-87.7383, -3.175)
  midpoint L3 P10
  midpoint L1 P11
  coincident L1 P12
  coincident L3 P13
  perpendicular L3 L6
  dimension "d194" distance L5 L6 = 3.175 (= "( 1 / 8 ) * 1 in")
  dimension "d195" Text1-Height = 9.525
extrude "Extrude10" add sketch "Branding Profile 4" along normal blind 0.3969 (= "( 1 / 64 ) * 1 in")
chamfer "Chamfer1" distance 0.3969 (= "( 1 / 64 ) * 1 in") Rotate Angle 25
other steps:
create_component "CreateComponent1"
create_component "CreateComponent2"
named bodies: "27491 #25 Horn", "27284 Orifice Pin #2"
